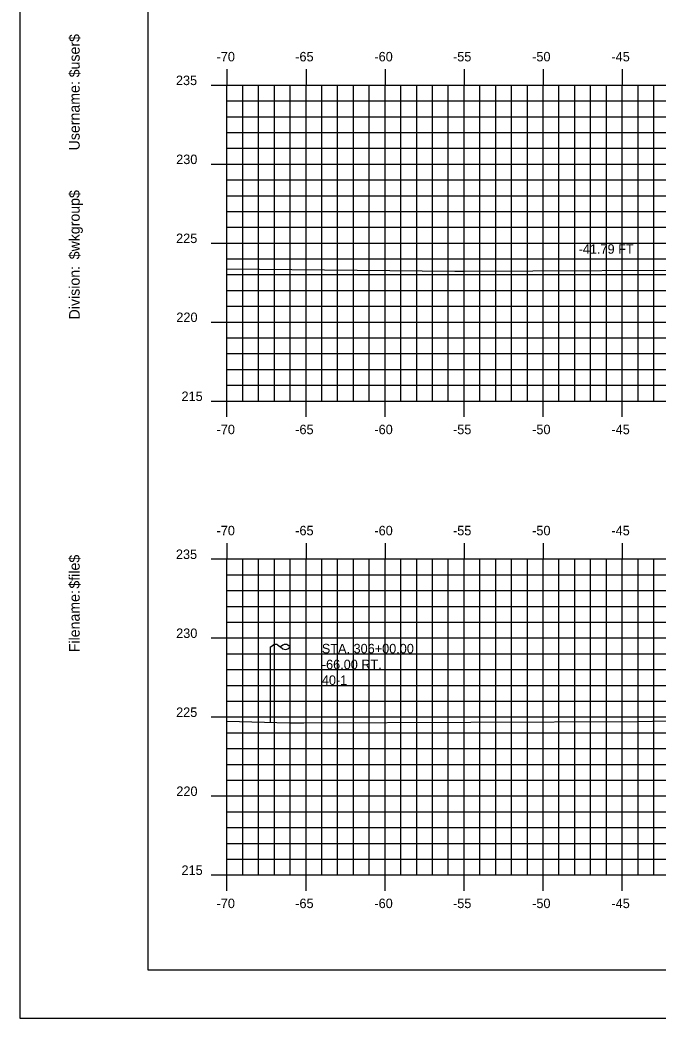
# Model space of a CAD drawing. Extents: x 1137433 to 1137603, y 608981 to 609091.
# Drawn here: x 1137432.6 to 1137472.9, y 608981.3 to 609044.5 of the extents above; entities that cross this region are included whole.
import ezdxf

# ---------------------------------------------------------------- set-up
doc = ezdxf.new("R2010")
doc.units = 0
for name, color, linetype in [('BORDER', 7, 'Continuous'), ('D_Text_Standard', 7, 'Continuous'), ('D_Utilities_Pole_Joint_Rt', 7, 'Continuous'), ('H_V ANNOTATION', 7, 'Continuous'), ('MAJOR', 7, 'Continuous'), ('MINOR', 7, 'Continuous'), ('PLOT BOUNDARY', 7, 'Continuous'), ('S_Roadway_Centerline', 7, 'Continuous')]:
    doc.layers.add(name, color=color, linetype=linetype)

msp = doc.modelspace()

# ---------------------------------------------------------------- linework, layer by layer
at = {"layer": 'BORDER'}
msp.add_lwpolyline([(1137440.653, 608984.335), (1137600.653, 608984.335), (1137600.653, 609089.335), (1137440.653, 609089.335)], close=True, dxfattribs=at)
at = {"layer": 'D_Utilities_Pole_Joint_Rt'}
for p, q in [((1137448.409, 609004.767), (1137448.565, 609004.877)), ((1137448.409, 609000.009), (1137448.409, 609004.767)), ((1137448.877, 609004.877), (1137449.034, 609004.767)), ((1137449.19, 609004.877), (1137449.034, 609004.767)), ((1137449.034, 609004.767), (1137449.19, 609004.656)), ((1137449.659, 609004.767), (1137449.503, 609004.877)), ((1137449.503, 609004.656), (1137449.659, 609004.767)), ((1137449.659, 609000.009), (1137449.659, 609004.767))]:
    msp.add_line(p, q, dxfattribs=at)
for centre, start, end in [((1137448.721, 609004.656), 90, 125.26439), ((1137448.721, 609004.656), 54.73561, 90), ((1137449.346, 609004.656), 90, 125.26439), ((1137449.346, 609004.877), 234.73561, 270), ((1137449.346, 609004.656), 54.73561, 90), ((1137449.346, 609004.877), 270, 305.26439)]:
    msp.add_arc(centre, 0.271, start, end, dxfattribs=at)
at = {"layer": 'MAJOR'}
for p, q in [((1137445.653, 609041.337), (1137445.653, 609040.335)), ((1137450.653, 609041.337), (1137450.653, 609040.335)), ((1137455.653, 609041.337), (1137455.653, 609040.335)), ((1137460.653, 609041.337), (1137460.653, 609040.335)), ((1137465.653, 609041.337), (1137465.653, 609040.335)), ((1137470.653, 609041.337), (1137470.653, 609040.335)), ((1137444.651, 609040.335), (1137445.653, 609040.335)), ((1137445.653, 609040.335), (1137585.653, 609040.335)), ((1137445.653, 609020.335), (1137445.653, 609040.335)), ((1137445.653, 609020.335), (1137445.653, 609040.335)), ((1137445.653, 609040.335), (1137585.653, 609040.335)), ((1137450.653, 609020.335), (1137450.653, 609040.335)), ((1137455.653, 609020.335), (1137455.653, 609040.335)), ((1137460.653, 609020.335), (1137460.653, 609040.335)), ((1137465.653, 609020.335), (1137465.653, 609040.335)), ((1137470.653, 609020.335), (1137470.653, 609040.335)), ((1137444.651, 609035.335), (1137445.653, 609035.335)), ((1137445.653, 609035.335), (1137585.653, 609035.335)), ((1137444.651, 609030.335), (1137445.653, 609030.335)), ((1137445.653, 609030.335), (1137585.653, 609030.335)), ((1137444.651, 609025.335), (1137445.653, 609025.335)), ((1137445.653, 609025.335), (1137585.653, 609025.335)), ((1137444.651, 609020.335), (1137445.653, 609020.335)), ((1137445.653, 609020.335), (1137585.653, 609020.335)), ((1137445.653, 609020.335), (1137585.653, 609020.335)), ((1137445.653, 609019.333), (1137445.653, 609020.335)), ((1137450.653, 609019.333), (1137450.653, 609020.335)), ((1137455.653, 609019.333), (1137455.653, 609020.335)), ((1137460.653, 609019.333), (1137460.653, 609020.335)), ((1137465.653, 609019.333), (1137465.653, 609020.335)), ((1137470.653, 609019.333), (1137470.653, 609020.335)), ((1137445.653, 609011.337), (1137445.653, 609010.335)), ((1137450.653, 609011.337), (1137450.653, 609010.335)), ((1137455.653, 609011.337), (1137455.653, 609010.335)), ((1137460.653, 609011.337), (1137460.653, 609010.335)), ((1137465.653, 609011.337), (1137465.653, 609010.335)), ((1137470.653, 609011.337), (1137470.653, 609010.335)), ((1137444.651, 609010.335), (1137445.653, 609010.335)), ((1137445.653, 609010.335), (1137585.653, 609010.335)), ((1137445.653, 608990.335), (1137445.653, 609010.335)), ((1137445.653, 608990.335), (1137445.653, 609010.335)), ((1137445.653, 609010.335), (1137585.653, 609010.335)), ((1137450.653, 608990.335), (1137450.653, 609010.335)), ((1137455.653, 608990.335), (1137455.653, 609010.335)), ((1137460.653, 608990.335), (1137460.653, 609010.335)), ((1137465.653, 608990.335), (1137465.653, 609010.335)), ((1137470.653, 608990.335), (1137470.653, 609010.335)), ((1137444.651, 609005.335), (1137445.653, 609005.335)), ((1137445.653, 609005.335), (1137585.653, 609005.335)), ((1137444.651, 609000.335), (1137445.653, 609000.335)), ((1137445.653, 609000.335), (1137585.653, 609000.335)), ((1137444.651, 608995.335), (1137445.653, 608995.335)), ((1137445.653, 608995.335), (1137585.653, 608995.335)), ((1137444.651, 608990.335), (1137445.653, 608990.335)), ((1137445.653, 608990.335), (1137585.653, 608990.335)), ((1137445.653, 608990.335), (1137585.653, 608990.335)), ((1137445.653, 608989.333), (1137445.653, 608990.335)), ((1137450.653, 608989.333), (1137450.653, 608990.335)), ((1137455.653, 608989.333), (1137455.653, 608990.335)), ((1137460.653, 608989.333), (1137460.653, 608990.335)), ((1137465.653, 608989.333), (1137465.653, 608990.335)), ((1137470.653, 608989.333), (1137470.653, 608990.335))]:
    msp.add_line(p, q, dxfattribs=at)
at = {"layer": 'MINOR'}
for p, q in [((1137446.653, 609020.335), (1137446.653, 609040.335)), ((1137447.653, 609020.335), (1137447.653, 609040.335)), ((1137448.653, 609020.335), (1137448.653, 609040.335)), ((1137449.653, 609020.335), (1137449.653, 609040.335)), ((1137451.653, 609020.335), (1137451.653, 609040.335)), ((1137452.653, 609020.335), (1137452.653, 609040.335)), ((1137453.653, 609020.335), (1137453.653, 609040.335)), ((1137454.653, 609020.335), (1137454.653, 609040.335)), ((1137456.653, 609020.335), (1137456.653, 609040.335)), ((1137457.653, 609020.335), (1137457.653, 609040.335)), ((1137458.653, 609020.335), (1137458.653, 609040.335)), ((1137459.653, 609020.335), (1137459.653, 609040.335)), ((1137461.653, 609020.335), (1137461.653, 609040.335)), ((1137462.653, 609020.335), (1137462.653, 609040.335)), ((1137463.653, 609020.335), (1137463.653, 609040.335)), ((1137464.653, 609020.335), (1137464.653, 609040.335)), ((1137466.653, 609020.335), (1137466.653, 609040.335)), ((1137467.653, 609020.335), (1137467.653, 609040.335)), ((1137468.653, 609020.335), (1137468.653, 609040.335)), ((1137469.653, 609020.335), (1137469.653, 609040.335)), ((1137471.653, 609020.335), (1137471.653, 609040.335)), ((1137472.653, 609020.335), (1137472.653, 609040.335)), ((1137445.653, 609039.335), (1137585.653, 609039.335)), ((1137445.653, 609039.335), (1137446.655, 609039.335)), ((1137445.653, 609038.335), (1137585.653, 609038.335)), ((1137445.653, 609038.335), (1137446.655, 609038.335)), ((1137445.653, 609037.335), (1137585.653, 609037.335)), ((1137445.653, 609037.335), (1137446.655, 609037.335)), ((1137445.653, 609036.335), (1137585.653, 609036.335)), ((1137445.653, 609036.335), (1137446.655, 609036.335)), ((1137445.653, 609034.335), (1137585.653, 609034.335)), ((1137445.653, 609034.335), (1137446.655, 609034.335)), ((1137445.653, 609033.335), (1137585.653, 609033.335)), ((1137445.653, 609033.335), (1137446.655, 609033.335)), ((1137445.653, 609032.335), (1137585.653, 609032.335)), ((1137445.653, 609032.335), (1137446.655, 609032.335)), ((1137445.653, 609031.335), (1137585.653, 609031.335)), ((1137445.653, 609031.335), (1137446.655, 609031.335)), ((1137445.653, 609029.335), (1137585.653, 609029.335)), ((1137445.653, 609029.335), (1137446.655, 609029.335)), ((1137445.653, 609028.335), (1137585.653, 609028.335)), ((1137445.653, 609028.335), (1137446.655, 609028.335)), ((1137445.653, 609027.335), (1137585.653, 609027.335)), ((1137445.653, 609027.335), (1137446.655, 609027.335)), ((1137445.653, 609026.335), (1137585.653, 609026.335)), ((1137445.653, 609026.335), (1137446.655, 609026.335)), ((1137445.653, 609024.335), (1137585.653, 609024.335)), ((1137445.653, 609024.335), (1137446.655, 609024.335)), ((1137445.653, 609023.335), (1137585.653, 609023.335)), ((1137445.653, 609023.335), (1137446.655, 609023.335)), ((1137445.653, 609022.335), (1137585.653, 609022.335)), ((1137445.653, 609022.335), (1137446.655, 609022.335)), ((1137445.653, 609021.335), (1137585.653, 609021.335)), ((1137445.653, 609021.335), (1137446.655, 609021.335)), ((1137446.653, 608990.335), (1137446.653, 609010.335)), ((1137447.653, 608990.335), (1137447.653, 609010.335)), ((1137448.653, 608990.335), (1137448.653, 609010.335)), ((1137449.653, 608990.335), (1137449.653, 609010.335)), ((1137451.653, 608990.335), (1137451.653, 609010.335)), ((1137452.653, 608990.335), (1137452.653, 609010.335)), ((1137453.653, 608990.335), (1137453.653, 609010.335)), ((1137454.653, 608990.335), (1137454.653, 609010.335)), ((1137456.653, 608990.335), (1137456.653, 609010.335)), ((1137457.653, 608990.335), (1137457.653, 609010.335)), ((1137458.653, 608990.335), (1137458.653, 609010.335)), ((1137459.653, 608990.335), (1137459.653, 609010.335)), ((1137461.653, 608990.335), (1137461.653, 609010.335)), ((1137462.653, 608990.335), (1137462.653, 609010.335)), ((1137463.653, 608990.335), (1137463.653, 609010.335)), ((1137464.653, 608990.335), (1137464.653, 609010.335)), ((1137466.653, 608990.335), (1137466.653, 609010.335)), ((1137467.653, 608990.335), (1137467.653, 609010.335)), ((1137468.653, 608990.335), (1137468.653, 609010.335)), ((1137469.653, 608990.335), (1137469.653, 609010.335)), ((1137471.653, 608990.335), (1137471.653, 609010.335)), ((1137472.653, 608990.335), (1137472.653, 609010.335)), ((1137445.653, 609009.335), (1137585.653, 609009.335)), ((1137445.653, 609009.335), (1137446.655, 609009.335)), ((1137445.653, 609008.335), (1137585.653, 609008.335)), ((1137445.653, 609008.335), (1137446.655, 609008.335)), ((1137445.653, 609007.335), (1137585.653, 609007.335)), ((1137445.653, 609007.335), (1137446.655, 609007.335)), ((1137445.653, 609006.335), (1137585.653, 609006.335)), ((1137445.653, 609006.335), (1137446.655, 609006.335)), ((1137445.653, 609004.335), (1137585.653, 609004.335)), ((1137445.653, 609004.335), (1137446.655, 609004.335)), ((1137445.653, 609003.335), (1137585.653, 609003.335)), ((1137445.653, 609003.335), (1137446.655, 609003.335)), ((1137445.653, 609002.335), (1137585.653, 609002.335)), ((1137445.653, 609002.335), (1137446.655, 609002.335)), ((1137445.653, 609001.335), (1137585.653, 609001.335)), ((1137445.653, 609001.335), (1137446.655, 609001.335)), ((1137445.653, 608999.335), (1137585.653, 608999.335)), ((1137445.653, 608999.335), (1137446.655, 608999.335)), ((1137445.653, 608998.335), (1137585.653, 608998.335)), ((1137445.653, 608998.335), (1137446.655, 608998.335)), ((1137445.653, 608997.335), (1137585.653, 608997.335)), ((1137445.653, 608997.335), (1137446.655, 608997.335)), ((1137445.653, 608996.335), (1137585.653, 608996.335)), ((1137445.653, 608996.335), (1137446.655, 608996.335)), ((1137445.653, 608994.335), (1137585.653, 608994.335)), ((1137445.653, 608994.335), (1137446.655, 608994.335)), ((1137445.653, 608993.335), (1137585.653, 608993.335)), ((1137445.653, 608993.335), (1137446.655, 608993.335)), ((1137445.653, 608992.335), (1137585.653, 608992.335)), ((1137445.653, 608992.335), (1137446.655, 608992.335)), ((1137445.653, 608991.335), (1137585.653, 608991.335)), ((1137445.653, 608991.335), (1137446.655, 608991.335))]:
    msp.add_line(p, q, dxfattribs=at)
at = {"layer": 'PLOT BOUNDARY'}
msp.add_lwpolyline([(1137432.56, 608981.276), (1137602.56, 608981.276), (1137602.56, 609091.276), (1137432.56, 609091.276)], close=True, dxfattribs=at)
at = {"layer": 'S_Roadway_Centerline'}
for points in [[(1137445.653, 609028.703), (1137460.066, 609028.556), (1137460.633, 609028.548), (1137478.111, 609028.646), (1137479.06, 609028.67), (1137486.804, 609028.946), (1137487.264, 609028.966), (1137498.159, 609031.27), (1137499.941, 609031.407), (1137500.381, 609031.497), (1137500.618, 609031.505), (1137510.823, 609031.631), (1137513.506, 609031.615), (1137521.857, 609031.577), (1137522.115, 609031.498), (1137522.315, 609031.418), (1137525.004, 609031.182), (1137525.888, 609031.035), (1137530.343, 609030.697), (1137531.057, 609030.727), (1137534.993, 609030.582), (1137537.95, 609030.665), (1137547.085, 609030.758)], [(1137445.653, 609000.068), (1137449.602, 608999.97), (1137450.522, 608999.958), (1137471.63, 609000.04), (1137476.229, 609000.162), (1137479.292, 609000.271), (1137487.646, 609000.636), (1137491.658, 609000.725), (1137493.508, 609000.954), (1137500.799, 609002.457), (1137507.803, 609002.706), (1137511.492, 609002.758), (1137515.564, 609002.741), (1137522.315, 609002.7), (1137524.764, 609002.536), (1137526.981, 609002.445), (1137539.217, 609001.937)]]:
    msp.add_lwpolyline(points, dxfattribs=at)

# ---------------------------------------------------------------- texts
at = {"layer": 'BORDER'}
for s, p in [('$user$', (1137436.338, 609040.827)), ('Username:', (1137436.338, 609036.203)), ('$wkgroup$', (1137436.338, 609029.305)), ('Division:', (1137436.338, 609025.501)), ('$file$', (1137436.338, 609008.461)), ('Filename:', (1137436.338, 609004.433))]:
    msp.add_text(s, height=0.6696, rotation=90, dxfattribs=at).set_placement(p)
at = {"layer": 'D_Text_Standard'}
for s, p in [('-41.79 FT', (1137467.896, 609029.66)), ('STA. 306+00.00', (1137451.653, 609004.363)), ('-66.00 RT.', (1137451.653, 609003.361)), ('40-1 ', (1137451.653, 609002.365))]:
    msp.add_text(s, height=0.6, dxfattribs=at).set_placement(p)
at = {"layer": 'H_V ANNOTATION'}
for s, p in [('-70', (1137444.994, 609041.835)), ('-65', (1137449.971, 609041.835)), ('-60', (1137454.979, 609041.835)), ('-55', (1137459.949, 609041.835)), ('-50', (1137464.957, 609041.835)), ('-45', (1137469.971, 609041.835)), ('235', (1137442.424, 609040.335)), ('230', (1137442.44, 609035.335)), ('225', (1137442.435, 609030.335)), ('220', (1137442.451, 609025.335)), ('215', (1137442.777, 609020.335)), ('-70', (1137444.994, 609018.235)), ('-65', (1137449.971, 609018.235)), ('-60', (1137454.979, 609018.235)), ('-55', (1137459.949, 609018.235)), ('-50', (1137464.957, 609018.235)), ('-45', (1137469.971, 609018.235)), ('-70', (1137444.994, 609011.835)), ('-65', (1137449.971, 609011.835)), ('-60', (1137454.979, 609011.835)), ('-55', (1137459.949, 609011.835)), ('-50', (1137464.957, 609011.835)), ('-45', (1137469.971, 609011.835)), ('235', (1137442.424, 609010.335)), ('230', (1137442.44, 609005.335)), ('225', (1137442.435, 609000.335)), ('220', (1137442.451, 608995.335)), ('215', (1137442.777, 608990.335)), ('-70', (1137444.994, 608988.235)), ('-65', (1137449.971, 608988.235)), ('-60', (1137454.979, 608988.235)), ('-55', (1137459.949, 608988.235)), ('-50', (1137464.957, 608988.235)), ('-45', (1137469.971, 608988.235))]:
    msp.add_text(s, height=0.6, dxfattribs=at).set_placement(p)
at = {"layer": 'MAJOR'}
for p in [(1137445.648, 609020.335), (1137445.648, 608990.335)]:
    msp.add_text('-', height=0.006, dxfattribs=at).set_placement(p)

doc.saveas('drawing.dxf')
